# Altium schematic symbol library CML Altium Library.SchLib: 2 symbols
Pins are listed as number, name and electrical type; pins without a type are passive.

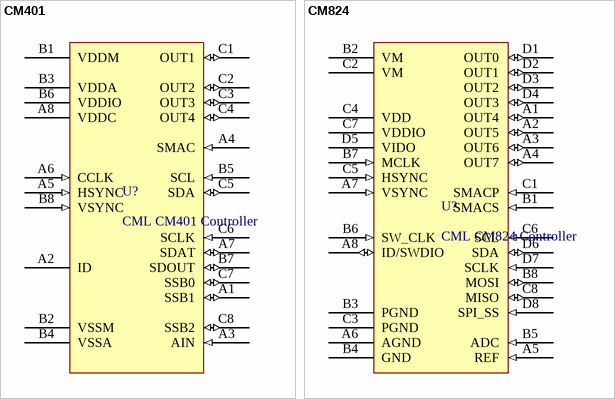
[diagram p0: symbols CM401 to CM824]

## CM401
designator U?, comment CML CM401 Controller
CML CM401 - 4 channel SMA Controller IC; Part Number: CN401; Contact Email: cml.electroniceng@cambridgemechatronics.com; SMA Channels: 4; Lenght: 3.5mm; Ball pitch: 0.4mm; Ball size: 0.17mm
footprint CM401 (CSP footprint for CM401)
pins: A1 SSB1 (io), A2 ID, A3 AIN (in), A4 SMAC (in), A5 HSYNC (in), A6 CCLK (in), A7 SDAT (io), A8 VDDC, B1 VDDM, B2 VSSM, B3 VDDA, B4 VSSA, B5 SCL (in), B6 VDDIO, B7 SDOUT (io), B8 VSYNC (in), C1 OUT1 (io), C2 OUT2 (io), C3 OUT3 (io), C4 OUT4 (io), C5 SDA (io), C6 SCLK (in), C7 SSB0 (io), C8 SSB2 (io)

## CM824
designator U?, comment CML CM824 Controller
CML CM824 - 8 channel SMA Controller IC; Contact Email: cml.electroniceng@cambridgemechatronics.com; SMA Channels: 8; Lenght: 4.2mm; Ball pitch: 0.4mm; Ball size: 0.17mm
footprint CM824 (LC898151 footprint for CM824)
pins: A1 OUT4 (io), A2 OUT5 (io), A3 OUT6 (io), A4 OUT7 (io), A5 REF (in), A6 AGND (power), A7 VSYNC (in), A8 ID/SWDIO (io), B1 SMACS (in), B2 VM (power), B3 PGND (power), B4 GND (power), B5 ADC (in), B6 SW_CLK (in), B7 MCLK (in), B8 MOSI (io), C1 SMACP (in), C2 VM (power), C3 PGND (power), C4 VDD (power), C5 HSYNC (in), C6 SCL (in), C7 VDDIO (power), C8 MISO (io), D1 OUT0 (io), D2 OUT1 (io), D3 OUT2 (io), D4 OUT3 (io), D5 VIDO (power), D6 SDA (io), D7 SCLK (in), D8 SPI_SS (in)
